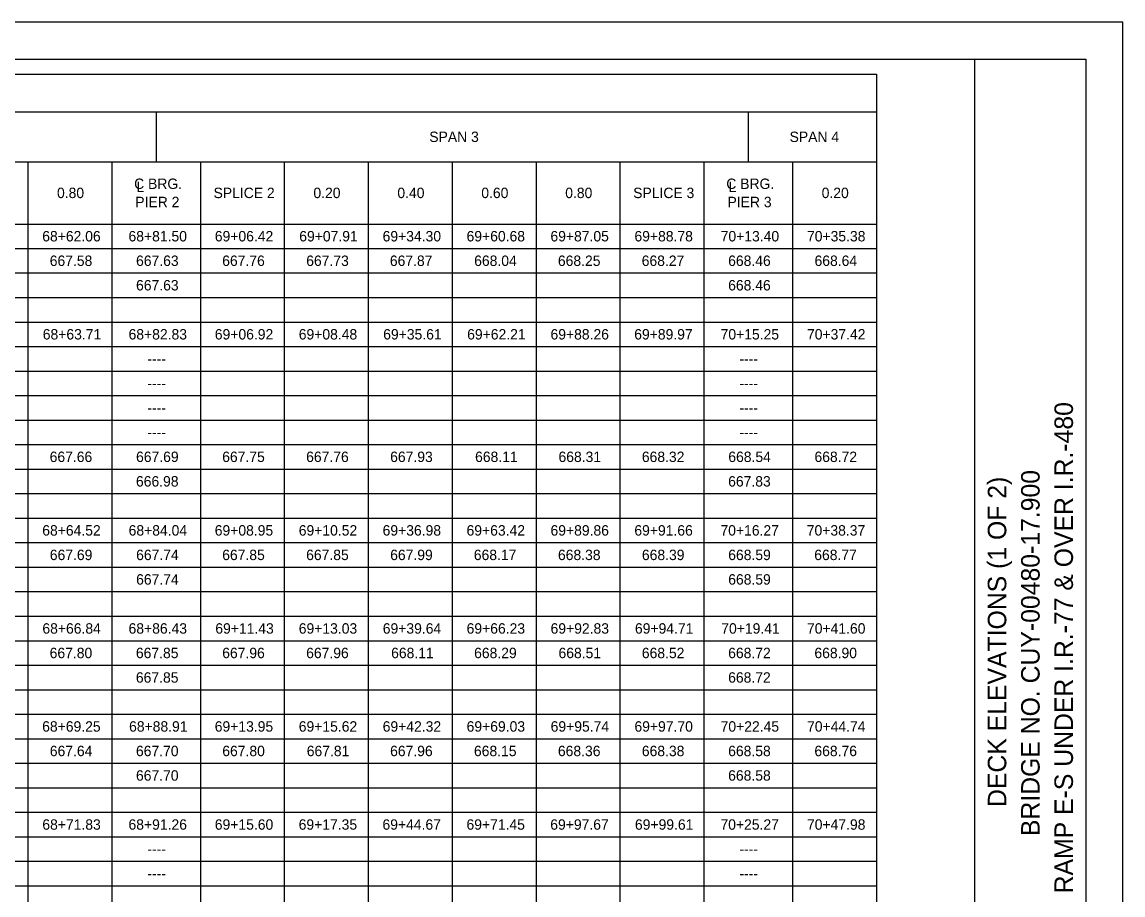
# Model space of a CAD drawing. Extents: x 0 to 34, y 0 to 22.
# Drawn here: x 19.14 to 34, y 10.21 to 22 of the extents above; entities that cross this region are included whole.
import ezdxf

# ---------------------------------------------------------------- set-up
doc = ezdxf.new("R2010")
doc.units = 0
for name, color, linetype in [('SH_Border', 7, 'Continuous'), ('SH_Cut_Line', 7, 'Continuous'), ('SH_Data', 7, 'Continuous'), ('SH_Text', 7, 'Continuous')]:
    doc.layers.add(name, color=color, linetype=linetype)

msp = doc.modelspace()

# ---------------------------------------------------------------- linework, layer by layer
at = {"layer": 'SH_Border'}
msp.add_line((32, 0.5), (32, 21.5), dxfattribs=at)
msp.add_lwpolyline([(1.5, 21.5), (33.5, 21.5), (33.5, 0.5), (1.5, 0.5)], close=True, dxfattribs=at)
at = {"layer": 'SH_Cut_Line'}
msp.add_lwpolyline([(0, 0), (34, 0), (34, 22), (0, 22)], close=True, dxfattribs=at)
at = {"layer": 'SH_Text'}
for p, q in [((2.8, 21.297), (30.673, 21.297)), ((30.673, 21.297), (30.673, 2.397)), ((2.8, 20.788), (30.673, 20.788)), ((20.949, 20.788), (20.949, 20.113)), ((28.942, 20.788), (28.942, 20.113)), ((2.8, 20.113), (30.673, 20.113)), ((19.218, 20.113), (19.218, 2.397)), ((20.351, 20.113), (20.351, 2.397)), ((21.547, 20.113), (21.547, 2.397)), ((22.68, 20.113), (22.68, 2.397)), ((23.813, 20.113), (23.813, 2.397)), ((24.945, 20.113), (24.945, 2.397)), ((26.078, 20.113), (26.078, 2.397)), ((27.211, 20.113), (27.211, 2.397)), ((28.343, 20.113), (28.343, 2.397)), ((29.54, 20.113), (29.54, 2.397)), ((2.8, 19.273), (30.673, 19.273)), ((4.2, 18.943), (30.673, 18.943)), ((4.2, 18.612), (30.673, 18.612)), ((2.8, 18.281), (30.673, 18.281)), ((2.8, 17.95), (30.673, 17.95)), ((4.2, 17.619), (30.673, 17.619)), ((4.2, 17.288), (30.673, 17.288)), ((4.2, 16.957), (30.673, 16.957)), ((4.2, 16.626), (30.673, 16.626)), ((4.2, 16.295), (30.673, 16.295)), ((4.2, 15.964), (30.673, 15.964)), ((2.8, 15.633), (30.673, 15.633)), ((2.8, 15.303), (30.673, 15.303)), ((4.2, 14.972), (30.673, 14.972)), ((4.2, 14.641), (30.673, 14.641)), ((2.8, 14.31), (30.673, 14.31)), ((2.8, 13.979), (30.673, 13.979)), ((4.2, 13.648), (30.673, 13.648)), ((4.2, 13.317), (30.673, 13.317)), ((2.8, 12.986), (30.673, 12.986)), ((2.8, 12.655), (30.673, 12.655)), ((4.2, 12.324), (30.673, 12.324)), ((4.2, 11.993), (30.673, 11.993)), ((2.8, 11.663), (30.673, 11.663)), ((2.8, 11.332), (30.673, 11.332)), ((4.2, 11.001), (30.673, 11.001)), ((4.2, 10.67), (30.673, 10.67)), ((4.2, 10.339), (30.673, 10.339))]:
    msp.add_line(p, q, dxfattribs=at)

# ---------------------------------------------------------------- texts
at = {"layer": 'SH_Data'}
for s, p in [('RAMP E-S UNDER I.R.-77 & OVER I.R.-480', (33.325, 10.237)), ('BRIDGE NO. CUY-00480-17.900', (32.875, 11.01)), ('DECK ELEVATIONS (1 OF 2)', (32.425, 11.403))]:
    msp.add_text(s, height=0.25, rotation=90, dxfattribs=at).set_placement(p)
at = {"layer": 'SH_Text'}
for s, height, p in [('SPAN 3', 0.1405, (24.637, 20.38)), ('SPAN 4', 0.1405, (29.5, 20.38)), ('0.80', 0.1405, (19.612, 19.623)), ('C BRG.        ', 0.14051, (20.653, 19.746)), ('L', 0.14, (20.684, 19.705)), ('SPLICE 2', 0.1405, (21.725, 19.623)), ('0.20', 0.1405, (23.073, 19.623)), ('0.40', 0.1405, (24.206, 19.623)), ('0.60', 0.1405, (25.339, 19.623)), ('0.80', 0.1405, (26.472, 19.623)), ('SPLICE 3', 0.1405, (27.389, 19.623)), ('C BRG.         ', 0.14051, (28.646, 19.746)), ('L', 0.14, (28.677, 19.705)), ('0.20', 0.1405, (29.933, 19.623)), ('PIER 2', 0.1405, (20.669, 19.5)), ('PIER 3', 0.1405, (28.662, 19.5)), ('68+62.06', 0.1405, (19.413, 19.038)), ('68+81.50', 0.1405, (20.577, 19.038)), ('69+06.42', 0.1405, (21.742, 19.038)), ('69+07.91', 0.1405, (22.882, 19.038)), ('69+34.30', 0.1405, (24.007, 19.038)), ('69+60.68', 0.1405, (25.14, 19.038)), ('69+87.05', 0.1405, (26.272, 19.038)), ('69+88.78', 0.1405, (27.406, 19.038)), ('70+13.40', 0.1405, (28.57, 19.038)), ('70+35.38', 0.1405, (29.735, 19.038)), ('667.58', 0.1405, (19.514, 18.707)), ('667.63', 0.1405, (20.679, 18.707)), ('667.76', 0.1405, (21.842, 18.707)), ('667.73', 0.1405, (22.976, 18.707)), ('667.87', 0.1405, (24.105, 18.707)), ('668.04', 0.1405, (25.243, 18.707)), ('668.25', 0.1405, (26.373, 18.707)), ('668.27', 0.1405, (27.504, 18.707)), ('668.46', 0.1405, (28.671, 18.707)), ('668.64', 0.1405, (29.837, 18.707)), ('667.63', 0.1405, (20.679, 18.376)), ('668.46', 0.1405, (28.671, 18.376)), ('68+63.71', 0.1405, (19.42, 17.714)), ('68+82.83', 0.1405, (20.578, 17.714)), ('69+06.92', 0.1405, (21.742, 17.714)), ('69+08.48', 0.1405, (22.875, 17.714)), ('69+35.61', 0.1405, (24.015, 17.714)), ('69+62.21', 0.1405, (25.148, 17.714)), ('69+88.26', 0.1405, (26.273, 17.714)), ('69+89.97', 0.1405, (27.403, 17.714)), ('70+15.25', 0.1405, (28.569, 17.714)), ('70+37.42', 0.1405, (29.735, 17.714)), ('----', 0.1405, (20.831, 17.383)), ('----', 0.1405, (28.824, 17.383)), ('----', 0.1405, (20.831, 17.052)), ('----', 0.1405, (28.824, 17.052)), ('----', 0.1405, (20.831, 16.721)), ('----', 0.1405, (28.824, 16.721)), ('----', 0.1405, (20.831, 16.39)), ('----', 0.1405, (28.824, 16.39)), ('667.66', 0.1405, (19.513, 16.06)), ('667.69', 0.1405, (20.679, 16.06)), ('667.75', 0.1405, (21.842, 16.06)), ('667.76', 0.1405, (22.975, 16.06)), ('667.93', 0.1405, (24.109, 16.06)), ('668.11', 0.1405, (25.255, 16.06)), ('668.31', 0.1405, (26.381, 16.06)), ('668.32', 0.1405, (27.506, 16.06)), ('668.54', 0.1405, (28.673, 16.06)), ('668.72', 0.1405, (29.836, 16.06)), ('666.98', 0.1405, (20.678, 15.729)), ('667.83', 0.1405, (28.671, 15.729)), ('68+64.52', 0.1405, (19.413, 15.067)), ('68+84.04', 0.1405, (20.579, 15.067)), ('69+08.95', 0.1405, (21.741, 15.067)), ('69+10.52', 0.1405, (22.875, 15.067)), ('69+36.98', 0.1405, (24.007, 15.067)), ('69+63.42', 0.1405, (25.14, 15.067)), ('69+89.86', 0.1405, (26.273, 15.067)), ('69+91.66', 0.1405, (27.405, 15.067)), ('70+16.27', 0.1405, (28.567, 15.067)), ('70+38.37', 0.1405, (29.732, 15.067)), ('667.69', 0.1405, (19.515, 14.736)), ('667.74', 0.1405, (20.68, 14.736)), ('667.85', 0.1405, (21.842, 14.736)), ('667.85', 0.1405, (22.975, 14.736)), ('667.99', 0.1405, (24.109, 14.736)), ('668.17', 0.1405, (25.238, 14.736)), ('668.38', 0.1405, (26.374, 14.736)), ('668.39', 0.1405, (27.507, 14.736)), ('668.59', 0.1405, (28.672, 14.736)), ('668.77', 0.1405, (29.833, 14.736)), ('667.74', 0.1405, (20.68, 14.405)), ('668.59', 0.1405, (28.672, 14.405)), ('68+66.84', 0.1405, (19.415, 13.743)), ('68+86.43', 0.1405, (20.578, 13.743)), ('69+11.43', 0.1405, (21.749, 13.743)), ('69+13.03', 0.1405, (22.875, 13.743)), ('69+39.64', 0.1405, (24.009, 13.743)), ('69+66.23', 0.1405, (25.141, 13.743)), ('69+92.83', 0.1405, (26.274, 13.743)), ('69+94.71', 0.1405, (27.413, 13.743)), ('70+19.41', 0.1405, (28.578, 13.743)), ('70+41.60', 0.1405, (29.735, 13.743)), ('667.80', 0.1405, (19.513, 13.412)), ('667.85', 0.1405, (20.677, 13.412)), ('667.96', 0.1405, (21.842, 13.412)), ('667.96', 0.1405, (22.975, 13.412)), ('668.11', 0.1405, (24.122, 13.412)), ('668.29', 0.1405, (25.242, 13.412)), ('668.51', 0.1405, (26.381, 13.412)), ('668.52', 0.1405, (27.506, 13.412)), ('668.72', 0.1405, (28.671, 13.412)), ('668.90', 0.1405, (29.835, 13.412)), ('667.85', 0.1405, (20.677, 13.081)), ('668.72', 0.1405, (28.671, 13.081)), ('68+69.25', 0.1405, (19.412, 12.42)), ('68+88.91', 0.1405, (20.585, 12.42)), ('69+13.95', 0.1405, (21.741, 12.42)), ('69+15.62', 0.1405, (22.875, 12.42)), ('69+42.32', 0.1405, (24.008, 12.42)), ('69+69.03', 0.1405, (25.141, 12.42)), ('69+95.74', 0.1405, (26.275, 12.42)), ('69+97.70', 0.1405, (27.406, 12.42)), ('70+22.45', 0.1405, (28.569, 12.42)), ('70+44.74', 0.1405, (29.736, 12.42)), ('667.64', 0.1405, (19.515, 12.089)), ('667.70', 0.1405, (20.678, 12.089)), ('667.80', 0.1405, (21.843, 12.089)), ('667.81', 0.1405, (22.983, 12.089)), ('667.96', 0.1405, (24.108, 12.089)), ('668.15', 0.1405, (25.24, 12.089)), ('668.36', 0.1405, (26.373, 12.089)), ('668.38', 0.1405, (27.506, 12.089)), ('668.58', 0.1405, (28.671, 12.089)), ('668.76', 0.1405, (29.835, 12.089)), ('667.70', 0.1405, (20.678, 11.758)), ('668.58', 0.1405, (28.671, 11.758)), ('68+71.83', 0.1405, (19.414, 11.096)), ('68+91.26', 0.1405, (20.577, 11.096)), ('69+15.60', 0.1405, (21.742, 11.096)), ('69+17.35', 0.1405, (22.874, 11.096)), ('69+44.67', 0.1405, (24.005, 11.096)), ('69+71.45', 0.1405, (25.139, 11.096)), ('69+97.67', 0.1405, (26.27, 11.096)), ('69+99.61', 0.1405, (27.413, 11.096)), ('70+25.27', 0.1405, (28.567, 11.096)), ('70+47.98', 0.1405, (29.735, 11.096)), ('----', 0.1405, (20.831, 10.765)), ('----', 0.1405, (28.824, 10.765)), ('----', 0.1405, (20.831, 10.434)), ('----', 0.1405, (28.824, 10.434))]:
    msp.add_text(s, height=height, dxfattribs=at).set_placement(p)

doc.saveas('drawing.dxf')
